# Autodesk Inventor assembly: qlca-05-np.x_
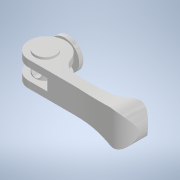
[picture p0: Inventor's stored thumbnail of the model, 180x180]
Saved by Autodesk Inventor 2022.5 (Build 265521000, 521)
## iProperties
Created: 2023-06
Part Number: qlca-05-np.x_
Document SubType Name: Assembly
Designer: ImaoCorp
Sending System: SOLIDWORKS 2021-2021301
MC: AMD64
MC_MODEL: Intel64 Family 6 Model 60 Stepping 3, GenuineIntel
OS: Windows_NT
FRU: Parasolid Version 32.1, build 255,  1- 1-2021
FORMAT: text
GUISE: transmit
KEY: qlca-05-np
FILE: qlca-05-np.x_t
DATE: Thu Jun 15 16:14:34 2023
Author: ImaoCorp
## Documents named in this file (4)
- X:\14_SW2022-Inv2022\00_全2023-1023新製品(TCC)まで\q\qlca-05-np\QLCA-05-NP.iam
- X:\14_SW2022-Inv2022\00_全2023-1023新製品(TCC)まで\q\qlca-05-np\qlca-05-np_01.ipt
- X:\14_SW2022-Inv2022\00_全2023-1023新製品(TCC)まで\q\qlca-05-np\qlca-05-np_02.ipt
- X:\14_SW2022-Inv2022\00_全2023-1023新製品(TCC)まで\q\qlca-05-np\qlca-05-np_03.ipt
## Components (3 placed, 3 different names)
1. qlca-05-np_01
2. qlca-05-np_02
3. qlca-05-np_03
